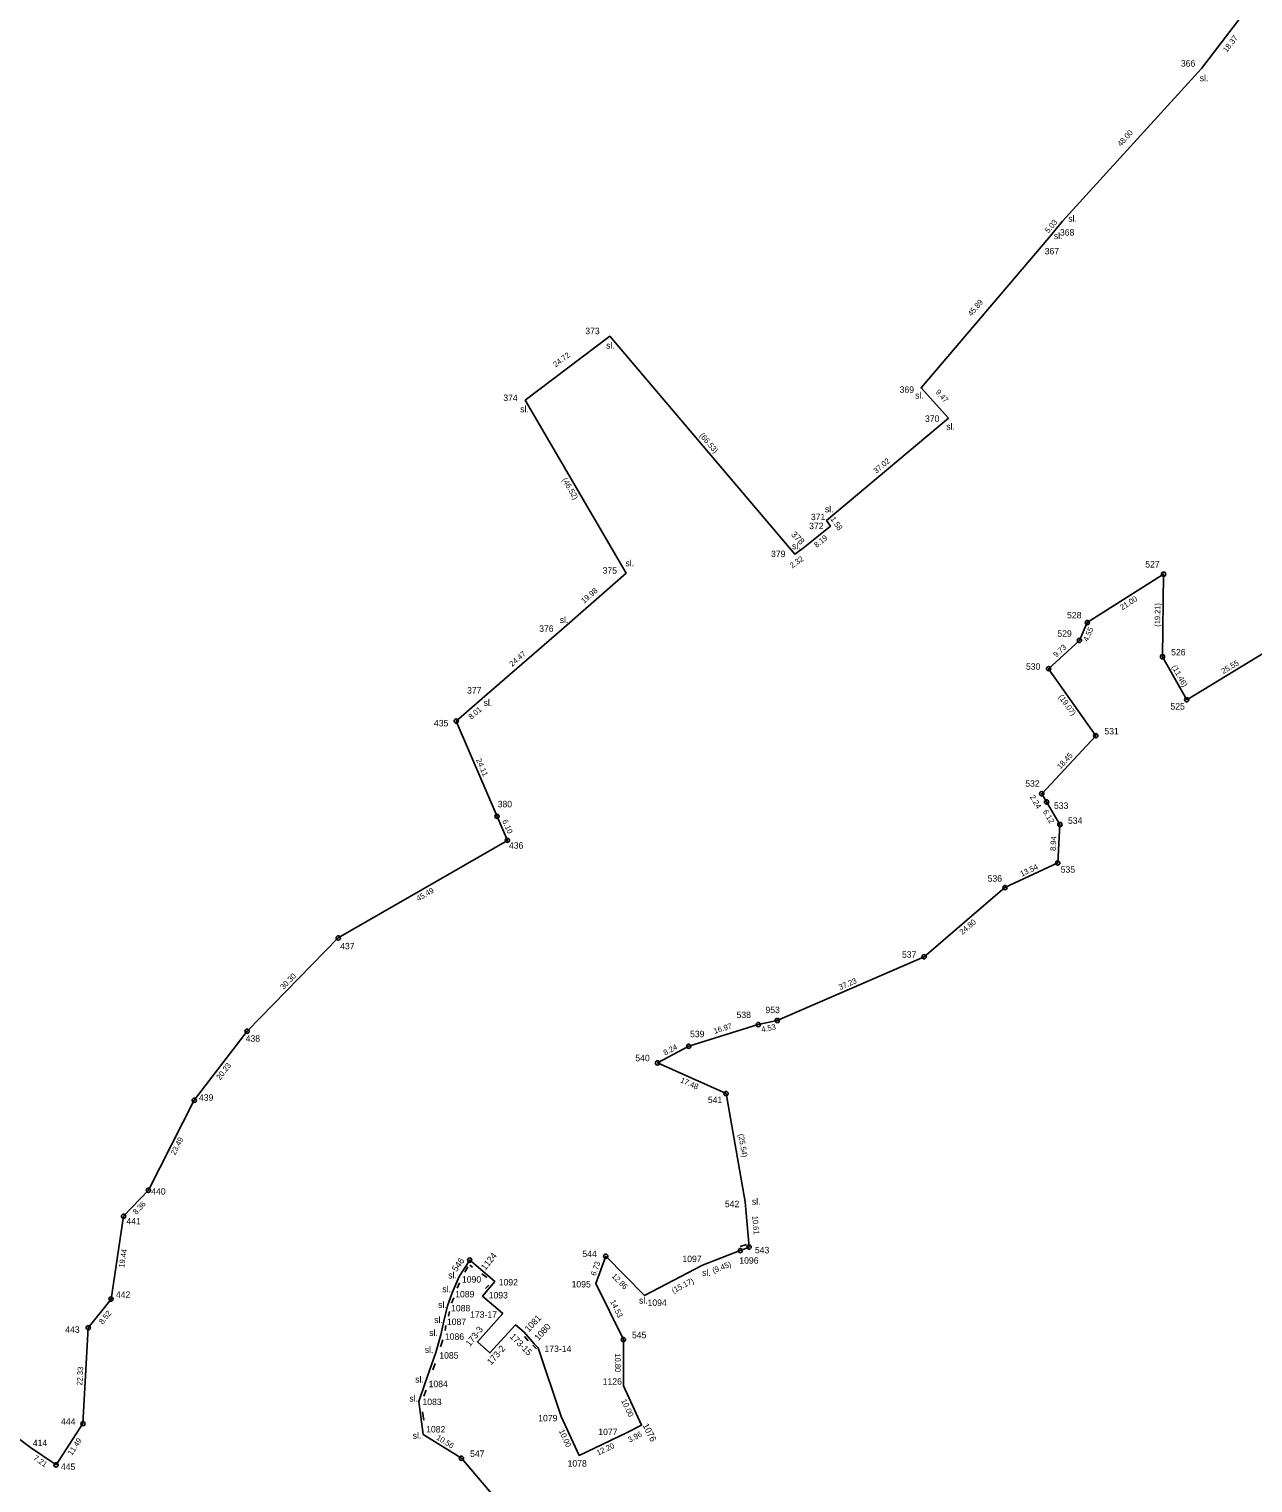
# Model space of a CAD drawing. Extents: x -555170 to -550532, y -1039598 to -1034701.
# Drawn here: x -553793.6 to -553508.8, y -1037480.9 to -1037142.8 of the extents above; entities that cross this region are included whole.
import ezdxf

# ---------------------------------------------------------------- set-up
doc = ezdxf.new("R2010")
doc.units = 0
for name, color, linetype in [('Vrstva 10', 7, 'Continuous'), ('Vrstva 40', 7, 'Continuous'), ('Vrstva 43', 7, 'Continuous'), ('Vrstva 48', 7, 'Continuous')]:
    doc.layers.add(name, color=color, linetype=linetype)

msp = doc.modelspace()

# ---------------------------------------------------------------- linework, layer by layer
at = {"layer": 'Vrstva 10'}
for p, q in [((-553626.65, -1037425.47), (-553628.11, -1037425.99)), ((-553691.47, -1037430.72), (-553692.22, -1037431.96)), ((-553691.05, -1037430.3), (-553690.41, -1037430.76)), ((-553688.22, -1037432.33), (-553687.09, -1037433.15)), ((-553693.42, -1037434.41), (-553693.96, -1037435.65)), ((-553686.6, -1037434.92), (-553687.38, -1037435.7)), ((-553694.78, -1037437.89), (-553695.26, -1037439.12)), ((-553695.78, -1037441.05), (-553696.01, -1037442.13)), ((-553696.6, -1037444.3), (-553696.79, -1037445.53)), ((-553697.31, -1037447.65), (-553697.87, -1037449.33)), ((-553678.28, -1037446.91), (-553677.42, -1037447.9)), ((-553676.36, -1037448.9), (-553675.54, -1037449.74)), ((-553699.06, -1037453.18), (-553699.66, -1037454.63)), ((-553701.22, -1037459.35), (-553701.7, -1037460.76)), ((-553702.02, -1037464.43), (-553701.76, -1037466.36))]:
    msp.add_line(p, q, dxfattribs=at)
at = {"layer": 'Vrstva 40'}
for p, q in [((-553509.6, -1037137.44), (-553520.8, -1037152.01)), ((-553520.8, -1037152.01), (-553553.12, -1037187.5)), ((-553553.12, -1037187.5), (-553556.34, -1037191.38)), ((-553556.34, -1037191.38), (-553586.04, -1037226.31)), ((-553658.45, -1037214.25), (-553678.13, -1037229.18)), ((-553615.38, -1037264.96), (-553658.45, -1037214.25)), ((-553586.04, -1037226.31), (-553579.65, -1037233.3)), ((-553678.13, -1037229.18), (-553654.67, -1037269.35)), ((-553579.65, -1037233.3), (-553608.01, -1037257.14)), ((-553608.01, -1037257.14), (-553607.12, -1037258.44)), ((-553607.12, -1037258.44), (-553613.48, -1037263.6)), ((-553613.48, -1037263.6), (-553615.38, -1037264.96)), ((-553654.67, -1037269.35), (-553669.66, -1037282.52)), ((-553547.35, -1037280.86), (-553529.61, -1037269.61)), ((-553529.61, -1037269.61), (-553529.85, -1037288.81)), ((-553549.19, -1037285.03), (-553547.35, -1037280.86)), ((-553669.66, -1037282.52), (-553688.16, -1037298.52)), ((-553556.38, -1037291.59), (-553549.19, -1037285.03)), ((-553524.22, -1037298.8), (-553502.37, -1037285.57)), ((-553529.85, -1037288.81), (-553524.22, -1037298.8)), ((-553545.38, -1037307.17), (-553556.38, -1037291.59)), ((-553688.16, -1037298.52), (-553694.18, -1037303.78)), ((-553694.18, -1037303.78), (-553684.67, -1037325.93)), ((-553557.95, -1037320.67), (-553545.38, -1037307.17)), ((-553556.82, -1037322.58), (-553557.95, -1037320.67)), ((-553553.72, -1037327.83), (-553556.82, -1037322.58)), ((-553684.67, -1037325.93), (-553682.27, -1037331.51)), ((-553554.22, -1037336.76), (-553553.72, -1037327.83)), ((-553682.27, -1037331.51), (-553721.65, -1037354.21)), ((-553566.51, -1037342.51), (-553554.22, -1037336.76)), ((-553585.33, -1037358.59), (-553566.51, -1037342.51)), ((-553721.65, -1037354.21), (-553742.86, -1037375.91)), ((-553619.5, -1037373.41), (-553585.33, -1037358.59)), ((-553640.09, -1037379.39), (-553623.91, -1037374.36)), ((-553623.91, -1037374.36), (-553619.5, -1037373.41)), ((-553742.86, -1037375.91), (-553755.14, -1037391.96)), ((-553647.36, -1037383.28), (-553640.09, -1037379.39)), ((-553631.41, -1037390.4), (-553647.36, -1037383.28)), ((-553755.14, -1037391.96), (-553765.81, -1037412.88)), ((-553626.96, -1037415.55), (-553631.41, -1037390.4)), ((-553765.81, -1037412.88), (-553771.58, -1037418.93)), ((-553626.04, -1037426.11), (-553626.96, -1037415.55)), ((-553771.58, -1037418.93), (-553774.51, -1037438.18)), ((-553628.09, -1037426.92), (-553626.04, -1037426.11)), ((-553693.5, -1037432.94), (-553691.06, -1037429.12)), ((-553691.06, -1037429.12), (-553689.1, -1037430.78)), ((-553661.68, -1037434.58), (-553659.39, -1037428.24)), ((-553659.39, -1037428.24), (-553650.35, -1037437.33)), ((-553636.91, -1037430.3), (-553628.09, -1037426.92)), ((-553695.11, -1037436.76), (-553693.5, -1037432.94)), ((-553689.1, -1037430.78), (-553685.21, -1037434.07)), ((-553650.35, -1037437.33), (-553636.91, -1037430.3)), ((-553685.21, -1037434.07), (-553688.09, -1037437.48)), ((-553655.3, -1037447.6), (-553661.68, -1037434.58)), ((-553774.51, -1037438.18), (-553779.81, -1037444.85)), ((-553697.11, -1037443.33), (-553696.22, -1037439.78)), ((-553696.22, -1037439.78), (-553695.11, -1037436.76)), ((-553688.09, -1037437.48), (-553683.37, -1037441.54)), ((-553683.37, -1037441.54), (-553689.26, -1037448.13)), ((-553779.81, -1037444.85), (-553781.03, -1037467.16)), ((-553698.91, -1037450.62), (-553697.78, -1037446.53)), ((-553697.78, -1037446.53), (-553697.11, -1037443.33)), ((-553686.35, -1037450.72), (-553680.39, -1037444.21)), ((-553680.39, -1037444.21), (-553678.41, -1037445.9)), ((-553678.41, -1037445.9), (-553676.02, -1037448.59)), ((-553689.26, -1037448.13), (-553686.35, -1037450.72)), ((-553676.02, -1037448.59), (-553675.1, -1037449.51)), ((-553675.1, -1037449.51), (-553669.77, -1037465.47)), ((-553655.28, -1037458.4), (-553655.3, -1037447.6)), ((-553701.45, -1037457.66), (-553698.91, -1037450.62)), ((-553702.92, -1037462.01), (-553701.45, -1037457.66)), ((-553651.06, -1037467.48), (-553655.28, -1037458.4)), ((-553701.9, -1037469.66), (-553702.92, -1037462.01)), ((-553669.77, -1037465.47), (-553665.57, -1037474.54)), ((-553793.25, -1037472.71), (-553799.13, -1037468.33)), ((-553781.03, -1037467.16), (-553787.29, -1037476.76)), ((-553692.97, -1037475.2), (-553701.9, -1037469.66)), ((-553665.57, -1037474.54), (-553654.58, -1037469.3)), ((-553654.58, -1037469.3), (-553651.06, -1037467.48)), ((-553787.29, -1037476.76), (-553793.25, -1037472.71)), ((-553673.19, -1037498.45), (-553692.97, -1037475.2))]:
    msp.add_line(p, q, dxfattribs=at)
at = {"layer": 'Vrstva 43'}
for p, q in [((-553520.8, -1037152.01), (-553520.8, -1037152.01)), ((-553553.12, -1037187.5), (-553553.12, -1037187.5)), ((-553556.34, -1037191.38), (-553556.34, -1037191.38)), ((-553658.45, -1037214.25), (-553658.45, -1037214.25)), ((-553586.04, -1037226.31), (-553586.04, -1037226.31)), ((-553678.13, -1037229.18), (-553678.13, -1037229.18)), ((-553579.65, -1037233.3), (-553579.65, -1037233.3)), ((-553608.01, -1037257.14), (-553608.01, -1037257.14)), ((-553607.12, -1037258.44), (-553607.12, -1037258.44)), ((-553613.48, -1037263.6), (-553613.48, -1037263.6)), ((-553615.38, -1037264.96), (-553615.38, -1037264.96)), ((-553654.67, -1037269.35), (-553654.67, -1037269.35)), ((-553529.61, -1037269.61), (-553529.61, -1037269.61)), ((-553547.35, -1037280.86), (-553547.35, -1037280.86)), ((-553669.66, -1037282.52), (-553669.66, -1037282.52)), ((-553549.19, -1037285.03), (-553549.19, -1037285.03)), ((-553529.85, -1037288.81), (-553529.85, -1037288.81)), ((-553556.38, -1037291.59), (-553556.38, -1037291.59)), ((-553688.16, -1037298.52), (-553688.16, -1037298.52)), ((-553524.22, -1037298.8), (-553524.22, -1037298.8)), ((-553694.18, -1037303.78), (-553694.18, -1037303.78)), ((-553545.38, -1037307.17), (-553545.38, -1037307.17)), ((-553557.95, -1037320.67), (-553557.95, -1037320.67)), ((-553556.82, -1037322.58), (-553556.82, -1037322.58)), ((-553684.67, -1037325.93), (-553684.67, -1037325.93)), ((-553553.72, -1037327.83), (-553553.72, -1037327.83)), ((-553682.27, -1037331.51), (-553682.27, -1037331.51)), ((-553554.22, -1037336.76), (-553554.22, -1037336.76)), ((-553566.51, -1037342.51), (-553566.51, -1037342.51)), ((-553721.65, -1037354.21), (-553721.65, -1037354.21)), ((-553585.33, -1037358.59), (-553585.33, -1037358.59)), ((-553623.91, -1037374.36), (-553623.91, -1037374.36)), ((-553619.5, -1037373.41), (-553619.5, -1037373.41)), ((-553742.86, -1037375.91), (-553742.86, -1037375.91)), ((-553640.09, -1037379.39), (-553640.09, -1037379.39)), ((-553647.36, -1037383.28), (-553647.36, -1037383.28)), ((-553755.14, -1037391.96), (-553755.14, -1037391.96)), ((-553631.41, -1037390.4), (-553631.41, -1037390.4)), ((-553765.81, -1037412.88), (-553765.81, -1037412.88)), ((-553626.96, -1037415.55), (-553626.96, -1037415.55)), ((-553771.58, -1037418.93), (-553771.58, -1037418.93)), ((-553626.04, -1037426.11), (-553626.04, -1037426.11)), ((-553691.06, -1037429.12), (-553691.06, -1037429.12)), ((-553690.8, -1037428.72), (-553690.8, -1037428.72)), ((-553659.39, -1037428.24), (-553659.39, -1037428.24)), ((-553628.09, -1037426.92), (-553628.09, -1037426.92)), ((-553693.5, -1037432.94), (-553693.5, -1037432.94)), ((-553689.1, -1037430.78), (-553689.1, -1037430.78)), ((-553636.91, -1037430.3), (-553636.91, -1037430.3)), ((-553685.21, -1037434.07), (-553685.21, -1037434.07)), ((-553661.68, -1037434.58), (-553661.68, -1037434.58)), ((-553774.51, -1037438.18), (-553774.51, -1037438.18)), ((-553696.22, -1037439.78), (-553696.22, -1037439.78)), ((-553695.11, -1037436.76), (-553695.11, -1037436.76)), ((-553688.09, -1037437.48), (-553688.09, -1037437.48)), ((-553650.35, -1037437.33), (-553650.35, -1037437.33)), ((-553683.37, -1037441.54), (-553683.37, -1037441.54)), ((-553779.81, -1037444.85), (-553779.81, -1037444.85)), ((-553697.78, -1037446.53), (-553697.78, -1037446.53)), ((-553697.11, -1037443.33), (-553697.11, -1037443.33)), ((-553680.39, -1037444.21), (-553680.39, -1037444.21)), ((-553678.41, -1037445.9), (-553678.41, -1037445.9)), ((-553689.26, -1037448.13), (-553689.26, -1037448.13)), ((-553676.02, -1037448.59), (-553676.02, -1037448.59)), ((-553675.1, -1037449.51), (-553675.1, -1037449.51)), ((-553655.3, -1037447.6), (-553655.3, -1037447.6)), ((-553698.91, -1037450.62), (-553698.91, -1037450.62)), ((-553686.35, -1037450.72), (-553686.35, -1037450.72)), ((-553701.45, -1037457.66), (-553701.45, -1037457.66)), ((-553655.28, -1037458.4), (-553655.28, -1037458.4)), ((-553702.92, -1037462.01), (-553702.92, -1037462.01)), ((-553669.77, -1037465.47), (-553669.77, -1037465.47)), ((-553781.03, -1037467.16), (-553781.03, -1037467.16)), ((-553701.9, -1037469.66), (-553701.9, -1037469.66)), ((-553654.58, -1037469.3), (-553654.58, -1037469.3)), ((-553651.06, -1037467.48), (-553651.06, -1037467.48)), ((-553793.25, -1037472.71), (-553793.25, -1037472.71)), ((-553787.29, -1037476.76), (-553787.29, -1037476.76)), ((-553692.97, -1037475.2), (-553692.97, -1037475.2)), ((-553665.57, -1037474.54), (-553665.57, -1037474.54))]:
    msp.add_line(p, q, dxfattribs=at)
for centre, radius in [((-553529.61, -1037269.61), 0.5), ((-553529.61, -1037269.61), 0.01), ((-553547.35, -1037280.86), 0.5), ((-553547.35, -1037280.86), 0.01), ((-553549.19, -1037285.03), 0.5), ((-553549.19, -1037285.03), 0.01), ((-553556.38, -1037291.59), 0.5), ((-553529.86, -1037288.81), 0.5), ((-553529.86, -1037288.81), 0.01), ((-553556.38, -1037291.59), 0.01), ((-553524.22, -1037298.8), 0.5), ((-553524.22, -1037298.8), 0.01), ((-553694.18, -1037303.78), 0.5), ((-553694.18, -1037303.78), 0.01), ((-553545.38, -1037307.17), 0.5), ((-553545.38, -1037307.17), 0.01), ((-553557.95, -1037320.67), 0.5), ((-553557.95, -1037320.67), 0.01), ((-553556.82, -1037322.58), 0.5), ((-553556.82, -1037322.58), 0.01), ((-553684.67, -1037325.93), 0.5), ((-553684.67, -1037325.93), 0.01), ((-553553.72, -1037327.83), 0.5), ((-553553.72, -1037327.83), 0.01), ((-553682.27, -1037331.51), 0.5), ((-553682.27, -1037331.51), 0.01), ((-553554.22, -1037336.76), 0.5), ((-553554.22, -1037336.76), 0.01), ((-553566.51, -1037342.51), 0.5), ((-553566.51, -1037342.51), 0.01), ((-553721.65, -1037354.21), 0.5), ((-553721.65, -1037354.21), 0.01), ((-553585.33, -1037358.59), 0.5), ((-553585.33, -1037358.59), 0.01), ((-553742.86, -1037375.91), 0.5), ((-553623.91, -1037374.36), 0.5), ((-553623.91, -1037374.36), 0.01), ((-553619.5, -1037373.41), 0.5), ((-553619.5, -1037373.41), 0.01), ((-553742.86, -1037375.91), 0.01), ((-553640.1, -1037379.39), 0.5), ((-553640.1, -1037379.39), 0.01), ((-553647.36, -1037383.28), 0.5), ((-553647.36, -1037383.28), 0.01), ((-553755.14, -1037391.96), 0.5), ((-553755.14, -1037391.96), 0.01), ((-553631.41, -1037390.4), 0.5), ((-553631.41, -1037390.4), 0.01), ((-553765.81, -1037412.88), 0.5), ((-553765.81, -1037412.88), 0.01), ((-553771.58, -1037418.93), 0.5), ((-553771.58, -1037418.93), 0.01), ((-553626.04, -1037426.11), 0.5), ((-553626.04, -1037426.11), 0.01), ((-553691.06, -1037429.12), 0.5), ((-553691.06, -1037429.12), 0.01), ((-553659.39, -1037428.24), 0.5), ((-553659.39, -1037428.24), 0.01), ((-553628.09, -1037426.92), 0.5), ((-553628.09, -1037426.92), 0.01), ((-553774.51, -1037438.18), 0.5), ((-553774.51, -1037438.18), 0.01), ((-553779.81, -1037444.85), 0.5), ((-553779.81, -1037444.85), 0.01), ((-553655.3, -1037447.6), 0.5), ((-553655.3, -1037447.6), 0.01), ((-553781.03, -1037467.16), 0.5), ((-553781.03, -1037467.16), 0.01), ((-553787.29, -1037476.76), 0.5), ((-553787.29, -1037476.76), 0.01), ((-553692.97, -1037475.2), 0.5), ((-553692.97, -1037475.2), 0.01)]:
    msp.add_circle(centre, radius, dxfattribs=at)
at = {"layer": 'Vrstva 48'}
for points in [[(-553799.13, -1037468.33), (-553793.25, -1037472.71), (-553787.29, -1037476.76), (-553781.03, -1037467.16), (-553779.81, -1037444.85), (-553774.51, -1037438.18), (-553771.58, -1037418.93), (-553765.81, -1037412.88), (-553755.14, -1037391.96), (-553742.86, -1037375.91), (-553721.65, -1037354.21), (-553682.27, -1037331.51), (-553684.67, -1037325.93), (-553694.18, -1037303.78), (-553688.16, -1037298.52), (-553669.66, -1037282.52), (-553654.67, -1037269.35), (-553678.13, -1037229.18), (-553658.45, -1037214.25), (-553615.38, -1037264.96), (-553613.48, -1037263.6), (-553607.12, -1037258.44), (-553608.01, -1037257.14), (-553579.65, -1037233.3), (-553586.04, -1037226.31), (-553556.34, -1037191.38), (-553553.12, -1037187.5), (-553520.8, -1037152.01), (-553509.6, -1037137.44)], [(-553502.37, -1037285.57), (-553524.22, -1037298.8), (-553529.85, -1037288.81), (-553529.61, -1037269.61), (-553547.35, -1037280.86), (-553549.19, -1037285.03), (-553556.38, -1037291.59), (-553545.38, -1037307.17), (-553557.95, -1037320.67), (-553556.82, -1037322.58), (-553553.72, -1037327.83), (-553554.22, -1037336.76), (-553566.51, -1037342.51), (-553585.33, -1037358.59), (-553619.5, -1037373.41), (-553623.91, -1037374.36), (-553640.09, -1037379.39), (-553647.36, -1037383.28), (-553631.41, -1037390.4), (-553626.96, -1037415.55), (-553626.04, -1037426.11), (-553628.09, -1037426.92), (-553636.91, -1037430.3), (-553650.35, -1037437.33), (-553659.39, -1037428.24), (-553661.68, -1037434.58), (-553655.3, -1037447.6), (-553655.28, -1037458.4), (-553651.06, -1037467.48), (-553654.58, -1037469.3), (-553665.57, -1037474.54), (-553669.77, -1037465.47), (-553675.1, -1037449.51), (-553676.02, -1037448.59), (-553678.41, -1037445.9), (-553680.39, -1037444.21), (-553686.35, -1037450.72), (-553689.26, -1037448.13), (-553683.37, -1037441.54), (-553688.09, -1037437.48), (-553685.21, -1037434.07), (-553689.1, -1037430.78), (-553691.06, -1037429.12), (-553693.5, -1037432.94), (-553695.11, -1037436.76), (-553696.22, -1037439.78), (-553697.11, -1037443.33), (-553697.78, -1037446.53), (-553698.91, -1037450.62), (-553701.45, -1037457.66), (-553702.92, -1037462.01), (-553701.9, -1037469.66), (-553692.97, -1037475.2), (-553673.19, -1037498.45)]]:
    msp.add_lwpolyline(points, dxfattribs=at)

# ---------------------------------------------------------------- texts
at = {"layer": 'Vrstva 10'}
for s, rotation, p in [('18.37', 52.4504, (-553514.9, -1037148.37)), ('48.00', 47.6765, (-553539.55, -1037170.25)), ('5.03', 50.3108, (-553556.38, -1037190.41)), ('45.89', 49.6264, (-553574.32, -1037209.75)), ('24.72', 37.1853, (-553671.04, -1037221.56)), ('9.47', 312.4324, (-553582.77, -1037227.37)), ('(66.53)', 310.3426, (-553637.67, -1037237.42)), ('37.02', 40.0511, (-553596.46, -1037246.28)), ('(46.52)', 300.2857, (-553669.6, -1037247.65)), ('1.58', 304.3962, (-553607.19, -1037256.79)), ('8.19', 39.0531, (-553610.3, -1037263.53)), ('2.32', 35.5947, (-553616, -1037268.31)), ('19.98', 41.3021, (-553664.43, -1037276.5)), ('21.00', 32.3918, (-553539.25, -1037278.03)), ('(19.21)', 89.2559, (-553530.42, -1037281.84)), ('4.55', 66.0625, (-553547.22, -1037285.38)), ('24.47', 40.8554, (-553681.15, -1037291.2)), ('9.73', 42.4168, (-553554.57, -1037289.06)), ('(11.46)', 299.4402, (-553527.77, -1037291.19)), ('25.55', 31.1904, (-553515.68, -1037292.86)), ('(19.07)', 305.2421, (-553554.12, -1037298.17)), ('8.01', 41.1113, (-553690.67, -1037303.5)), ('18.45', 47.0474, (-553553.61, -1037315.06)), ('24.11', 293.2372, (-553689.6, -1037312.79)), ('2.24', 300.73, (-553560.8, -1037321.41)), ('6.12', 300.5679, (-553557.76, -1037324.83)), ('6.10', 293.2372, (-553683.5, -1037327)), ('8.94', 86.8097, (-553554.71, -1037334.01)), ('13.54', 25.0792, (-553562.61, -1037339.97)), ('45.49', 29.9647, (-553703.02, -1037345.72)), ('24.80', 40.4968, (-553576.42, -1037353.53)), ('30.30', 45.6435, (-553734.37, -1037366.29)), ('37.23', 23.4557, (-553604.86, -1037366.35)), ('16.97', 17.2733, (-553634.07, -1037376.52)), ('4.53', 12.1086, (-553623.04, -1037376.16)), ('8.24', 28.1661, (-553645.57, -1037381.58)), ('20.23', 52.5841, (-553749.11, -1037387.33)), ('17.48', 335.9231, (-553642.17, -1037387.73)), ('23.49', 62.9806, (-553759.59, -1037404.84)), ('(25.54)', 280.0385, (-553628.6, -1037399.89)), ('8.36', 46.357, (-553768.63, -1037418.65)), ('10.61', 274.9791, (-553625.33, -1037418.88)), ('19.44', 81.3456, (-553771.44, -1037430.97)), ('6.73', 70.1259, (-553661.76, -1037432.9)), ('(9.45)', 20.9678, (-553634.32, -1037432.21)), ('12.86', 314.8577, (-553658.11, -1037432.97)), ('(15.17)', 27.6125, (-553643.65, -1037436.9)), ('14.53', 296.0981, (-553658.42, -1037438.76)), ('8.52', 51.5196, (-553776.43, -1037444.17)), ('10.80', 270.1115, (-553657.24, -1037450.85)), ('22.33', 86.8857, (-553781.2, -1037458.31)), ('10.00', 294.927, (-553655.85, -1037461.8)), ('10.56', 328.183, (-553698.95, -1037470.72)), ('10.00', 294.8472, (-553670.35, -1037468.86)), ('3.96', 27.341, (-553653.82, -1037471.59)), ('11.49', 56.8663, (-553783.6, -1037474.68)), ('12.20', 25.4917, (-553661.17, -1037474.6)), ('7.21', 325.8027, (-553792.7, -1037475.44))]:
    msp.add_text(s, height=1.3, rotation=rotation, dxfattribs=at).set_placement(p)
at = {"layer": 'Vrstva 43'}
for s, p in [('366', (-553525.58, -1037151.57)), ('sl.', (-553521.2, -1037154.97)), ('sl.', (-553551.79, -1037187.67)), ('368', (-553553.72, -1037190.88)), ('sl.', (-553555.13, -1037191.69)), ('367', (-553557.27, -1037195.25)), ('373', (-553664.16, -1037213.8)), ('sl.', (-553659.3, -1037217.17)), ('369', (-553591.02, -1037227.44)), ('374', (-553683.23, -1037229.34)), ('sl.', (-553587.41, -1037228.78)), ('sl.', (-553679.3, -1037231.96)), ('370', (-553585.12, -1037234.2)), ('sl.', (-553580.18, -1037236.02)), ('sl.', (-553608.41, -1037255.22)), ('371', (-553611.66, -1037257.04)), ('372', (-553612.08, -1037259.14)), ('sl.', (-553616.07, -1037263.83)), ('sl.', (-553654.82, -1037267.79)), ('379', (-553620.94, -1037265.64)), ('527', (-553533.87, -1037268.06)), ('375', (-553660.13, -1037269.5)), ('sl.', (-553670.1, -1037280.97)), ('528', (-553552.06, -1037279.9)), ('376', (-553674.89, -1037283.02)), ('529', (-553554.32, -1037284.17)), ('526', (-553527.85, -1037288.51)), ('530', (-553561.63, -1037291.84)), ('377', (-553691.67, -1037297.37)), ('sl.', (-553687.82, -1037300.24)), ('525', (-553528.01, -1037301.1)), ('435', (-553699.37, -1037305)), ('531', (-553543.38, -1037306.87)), ('532', (-553561.79, -1037319.03)), ('380', (-553684.54, -1037323.83)), ('533', (-553555.11, -1037324.18)), ('534', (-553551.85, -1037327.67)), ('436', (-553681.92, -1037333.44)), ('535', (-553553.54, -1037339.03)), ('536', (-553570.55, -1037341.13)), ('437', (-553721.19, -1037356.86)), ('537', (-553590.48, -1037358.82)), ('538', (-553628.97, -1037372.84)), ('953', (-553622.24, -1037371.69)), ('438', (-553743.18, -1037378.33)), ('539', (-553639.79, -1037377.29)), ('540', (-553652.52, -1037382.88)), ('439', (-553754.05, -1037392.07)), ('541', (-553635.64, -1037392.62)), ('440', (-553765.14, -1037413.9)), ('542', (-553631.68, -1037416.82)), ('sl.', (-553625.4, -1037416.26)), ('441', (-553770.92, -1037420.83)), ('543', (-553624.69, -1037427.55)), ('544', (-553664.83, -1037428.41)), ('1097', (-553641.56, -1037429.59)), ('1096', (-553628.32, -1037429.97)), ('sl.', (-553696.05, -1037433.4)), ('1090', (-553692.85, -1037434.36)), ('sl.', (-553636.98, -1037432.79)), ('442', (-553773.37, -1037437.93)), ('sl.', (-553697.42, -1037436.62)), ('1089', (-553694.43, -1037437.8)), ('1093', (-553686.63, -1037438.05)), ('1092', (-553684.3, -1037435.03)), ('1095', (-553667.35, -1037435.49)), ('sl.', (-553698.38, -1037440.26)), ('1088', (-553695.39, -1037441.06)), ('sl.', (-553651.66, -1037439.25)), ('1094', (-553649.67, -1037439.79)), ('sl.', (-553699.31, -1037443.77)), ('1087', (-553696.35, -1037444.23)), ('173-17', (-553690.96, -1037442.54)), ('443', (-553785.15, -1037446.03)), ('sl.', (-553700.47, -1037446.79)), ('1086', (-553696.83, -1037447.67)), ('545', (-553653.3, -1037447.3)), ('sl.', (-553701.5, -1037450.7)), ('173-14', (-553673.66, -1037450.5)), ('1085', (-553698.12, -1037452.04)), ('sl.', (-553703.73, -1037457.63)), ('1126', (-553660.1, -1037458.1)), ('1084', (-553700.61, -1037458.68)), ('sl.', (-553705.08, -1037462.04)), ('1083', (-553702.04, -1037462.85)), ('444', (-553786.13, -1037467.4)), ('1079', (-553675.11, -1037466.62)), ('sl.', (-553704.32, -1037470.69)), ('1082', (-553701.18, -1037469.22)), ('1077', (-553661.13, -1037469.83)), ('414', (-553792.7, -1037472.38)), ('547', (-553690.97, -1037474.9)), ('445', (-553786.17, -1037477.93)), ('1078', (-553668.28, -1037477.16))]:
    msp.add_text(s, height=1.5, dxfattribs=at).set_placement(p)
for s, rotation, p in [('378', 315, (-553616.39, -1037260.52)), ('546', 54, (-553694.14, -1037431.98)), ('1124', 51.3, (-553687.42, -1037431.63)), ('1081', 46.8, (-553677.32, -1037445.96)), ('173-3', 52.2, (-553690.99, -1037449.33)), ('173-15', 315, (-553681.86, -1037447.03)), ('1080', 47.7, (-553675.06, -1037448)), ('173-2', 48.6, (-553686.05, -1037453.64)), ('1076', 297, (-553650.89, -1037467.56))]:
    msp.add_text(s, height=1.5, rotation=rotation, dxfattribs=at).set_placement(p)

doc.saveas('drawing.dxf')
